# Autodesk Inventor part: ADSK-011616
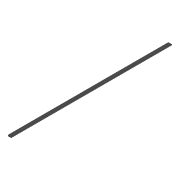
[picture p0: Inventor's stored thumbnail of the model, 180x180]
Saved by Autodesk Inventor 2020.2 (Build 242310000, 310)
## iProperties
Created: 2000-02
Part Number: ADSK-011616
Material: Pearson UHMW
Description: CHANEL,SU,AX,640,12,CHAIN GUIDE,HOPPER BED
Document SubType Name: Modeling
Designer: sspink
Density: 0.94 g/cm^3
Appearance: Silver
Mass: 331.18 g
Surface Area: 1593.8 cm^2
Volume: 352.319 cm^3
Control State: 0
Master: False
Checked Out: False
Shininess: 29.0
Length Units: 11269
Angle Units: 11279
Time Units: 11290
Mass Units: 11283
Length Display Precision: 3
Angle Display Precision: 2
Compacted: True
Cutlength: 64
Material Desc: WEAR STRIP,50 PITCH CHAIN
Material_Number: A102844
Dimensions: 9,5x1625x32 mm
Mass: 0,331 kg
VLT_Material: Pearson UHMW
Density: 0.94
Volumn: 5.6970652187500015
Area: 29.163248125000003
PropertySet Name: Model Information
Author: sspink
Revision Number: -
Title: CHANEL,SU,AX,640,12,CHAIN GUIDE,HOPPER BED
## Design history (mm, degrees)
node "Rectangular Pattern1" dims "d34" = 60, "d36" = 305
node "Solide1"
  node "Extrusion1" dims "d8" = 1625, "d9" = 0
  node "Extrusion2" dims "d11" = 25.4, "d12" = 0
  node "Extrusion3" dims "d14" = 25.4, "d15" = 0
  node "Hole2" dims "d26" = 6.6, "d27" = 12.6, "d28" = 6.35, "d29" = 90 deg, "d30" = 19.05, "d31" = 118 deg, "d41" = 6
  node "Extrusion4" dims "d32" = 25.4, "d33" = 0
sketch "Sketch1"
  geometry: L1 (-16, 0)-(16, 0); L2 (16, 0)-(16, 9.5); L3 (16, 9.5)-(10.5, 9.5); L4 (10.5, 9.5)-(10.5, 4.5); L5 (10.5, 4.5)-(4, 4.5); L6 (4, 4.5)-(4, 7); L7 (4, 7)-(-4, 7); L8 (-4, 7)-(-4, 4.5); L9 (-4, 4.5)-(-10.5, 4.5); L10 (-10.5, 4.5)-(-10.5, 9.5); L11 (-10.5, 9.5)-(-16, 9.5); L12 (-16, 9.5)-(-16, 0); 2 further points
  constraints: 24 end point, 10 parallel, 2 collinear, 1 coincident, 1 horizontal, 1 midpoint, 1 perpendicular
  dimensions: "d0" = 32 distance between parallel lines of L2 L12; "d2" = 12 distance between parallel lines of L8 L12; "d5" = 4.5 distance between parallel lines of L9 L1; "d6" = 9.5 distance between parallel lines of L11 L1; "d7" = 2.5 distance between parallel lines of L7 L9; "d37" = 12 distance between parallel lines of L2 L6 (= d2); "d38" = 5.5 distance of L10.end L11.end; "d39" = 5.5 distance of L2.end L3.end (= d38)
sketch "Sketch5"
  geometry: L1 (4.094, 2429.273)-(4.094, 820.727) reference; L2 (4.094, 812.5)-(-27.906, 812.5) reference; 4 further points; 1 other entity
  constraints: 1 horizontal alignment, 1 midpoint, 1 vertical alignment
  dimensions: "d40" = 50 distance from line of point (-11.906, 862.5) L2
sketch "Sketch7"
  geometry: A1 r 6.3 centre (-5.556, 862.5) between (-9.556, 867.367) and (-9.556, 857.633) reference; 2 further points
  constraints: 1 coincident, 3 other
node "Corps solides"
node "Corps surfaciques"
sketch "Sketch2"
  geometry: L1 (0, 9.5)-(0, 0) reference; L2 (1625, 9.5)-(0, 9.5) reference; L3 (0, 4.75)-(8.227, 9.5)
  constraints: 2 end point, 1 midpoint, 1 point on line
  dimensions: "d10" = 120 deg angle of L3 L1
sketch "Sketch3"
  geometry: L1 (1625, 0)-(1625, 9.5) reference; L2 (1625, 9.5)-(8.227, 9.5) reference; L3 (1625, 4.75)-(1616.773, 9.5)
  constraints: 2 end point, 1 midpoint, 1 point on line
  dimensions: "d13" = 120 deg angle of L1 L3
